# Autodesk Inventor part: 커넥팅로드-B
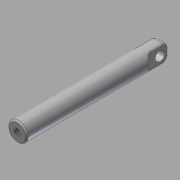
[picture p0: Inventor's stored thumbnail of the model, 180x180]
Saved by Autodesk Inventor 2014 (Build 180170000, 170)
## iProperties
Created: 2018-01
Part Number: 커넥팅로드-B
Material: 강철, 연강
Document SubType Name: Modeling
Designer: mduedu
Density: 1 g/cm^3
Appearance: 강철
Author: mduedu
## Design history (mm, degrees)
sketch "스케치1"
  geometry: C1 r 3.5 at (0, 0); 1 further point
  constraints: 1 centre point, 1 coincident
  dimensions: "d0" = 7 diameter of C1
extrude "돌출1" new body sketch "스케치1" distance "d1" = 53; taper "d2" = 0 deg
node "작업 평면1"
sketch "스케치2"
  geometry: L1 (-3.5, 0)-(3.5, 0) reference; L2 (4, 4)-(4, 0); L3 (4, 0)-(-4, 0); L4 (-4, 0)-(-4, 4); A1 r 4 centre (0, 4) between (4, 4) and (-4, 4); 2 further points
  constraints: 6 end point, 2 perpendicular, 2 point on circle, 2 tangent, 1 centre point, 1 collinear, 1 midpoint, 1 vertical, 1 vertical alignment
  dimensions: "d4" = 8 diameter of A1; "d5" = 4 distance from line of A1.centre L1
extrude "돌출2" cut sketch "스케치2" stored distance "d6" = 53; taper "d7" = 0 deg
fillet "모깎기1" dims "d8" = 2
fillet "모깎기2" dims "d9" = 0.5
fillet "모깎기3" dims "d10" = 0.5
sketch "스케치3"
  geometry: C1 r 1.75 at (0, 3); 1 further point
  constraints: 1 centre point, 1 vertical alignment
  dimensions: "d11" = 3.5 diameter of C1; "d12" = 3 distance of point (0, 0) C1.centre
extrude "돌출3" cut sketch "스케치3" stored distance "d13" = 53; taper "d14" = 0 deg
chamfer "모따기1" distance "d15" = 0.5; stored, may be unused: second distance "d16" = 2, angle "d17" = 45 deg
sketch "스케치4"
  geometry: 1 further point
hole "구멍1" sketch "스케치4" at (0, 0) diameter "d18" = 2.459; stored, may be unused: countersink angle "d22" = 90 deg, drill point angle "d24" = 120 deg; dims "d19" = 6.9, "d20" = 4, "d21" = 2, "d23" = 8.4
node "솔리드1"
mirror "대칭1"
other parameters: "d3" = 2
